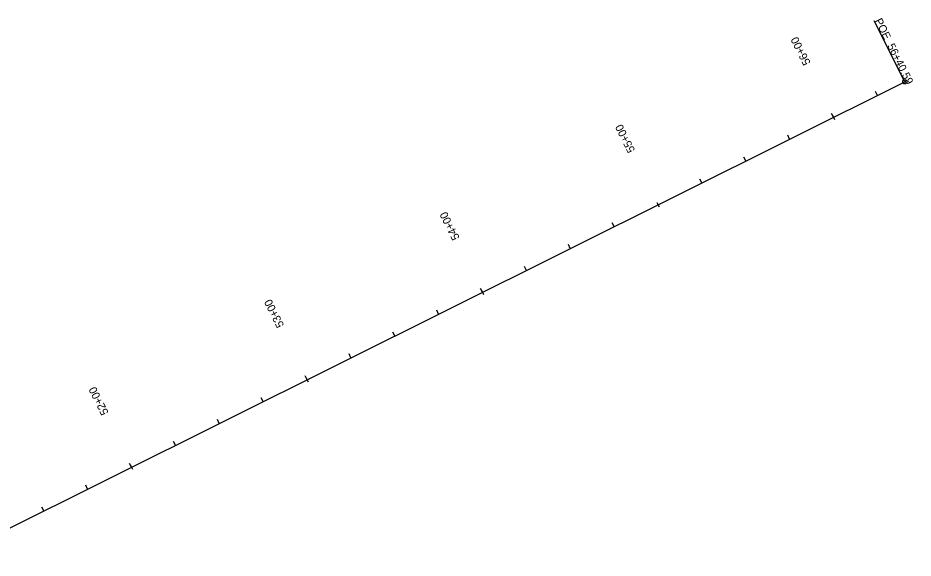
# Model space of a CAD drawing. Extents: x 21487884 to 21488802, y 8074558 to 8076894.
# Drawn here: x 21488345.4 to 21488801.9, y 8076618.7 to 8076894.3 of the extents above; entities that cross this region are included whole.
import ezdxf

# ---------------------------------------------------------------- set-up
doc = ezdxf.new("R2010")
doc.units = 0
for name, color, linetype in [('PS_BOLT', 7, 'Continuous'), ('PS_DIM', 7, 'Continuous'), ('PS_MID', 7, 'Continuous'), ('PS_SHAPE', 7, 'Continuous')]:
    doc.layers.add(name, color=color, linetype=linetype)

msp = doc.modelspace()

# ---------------------------------------------------------------- linework, layer by layer
at = {"layer": 'PS_BOLT'}
for p, q in [((21488761.31, 8076843.6), (21488760.33, 8076845.55)), ((21488671.27, 8076800.07), (21488672.36, 8076797.88)), ((21488582.32, 8076754.36), (21488581.35, 8076756.31)), ((21488492.83, 8076709.74), (21488491.85, 8076711.69)), ((21488403.33, 8076665.12), (21488402.36, 8076667.07))]:
    msp.add_line(p, q, dxfattribs=at)
at = {"layer": 'PS_DIM'}
msp.add_line((21488797.63, 8076861.71), (21488782.1, 8076892.86), dxfattribs=at)
msp.add_circle((21488797.63, 8076861.71), 1.07, dxfattribs=at)
at = {"layer": 'PS_MID'}
for p, q in [((21488783.68, 8076854.75), (21488782.7, 8076856.71)), ((21488760.76, 8076844.69), (21488761.85, 8076842.5)), ((21488738.93, 8076832.44), (21488737.96, 8076834.4)), ((21488716.56, 8076821.29), (21488715.58, 8076823.24)), ((21488694.19, 8076810.13), (21488693.21, 8076812.09)), ((21488671.27, 8076800.07), (21488672.36, 8076797.88)), ((21488649.44, 8076787.82), (21488648.46, 8076789.78)), ((21488627.07, 8076776.67), (21488626.09, 8076778.62)), ((21488604.69, 8076765.51), (21488603.72, 8076767.47)), ((21488581.77, 8076755.45), (21488582.87, 8076753.26)), ((21488559.95, 8076743.2), (21488558.97, 8076745.16)), ((21488537.57, 8076732.05), (21488536.6, 8076734)), ((21488515.2, 8076720.89), (21488514.23, 8076722.85)), ((21488492.28, 8076710.83), (21488493.37, 8076708.64)), ((21488470.45, 8076698.58), (21488469.48, 8076700.54)), ((21488448.08, 8076687.43), (21488447.11, 8076689.38)), ((21488425.71, 8076676.27), (21488424.73, 8076678.23)), ((21488402.79, 8076666.21), (21488403.88, 8076664.02)), ((21488380.96, 8076653.96), (21488379.99, 8076655.92)), ((21488358.59, 8076642.81), (21488357.61, 8076644.76))]:
    msp.add_line(p, q, dxfattribs=at)
at = {"layer": 'PS_SHAPE'}
msp.add_line((21488310.31, 8076618.73), (21488797.63, 8076861.71), dxfattribs=at)

# ---------------------------------------------------------------- texts
at = {"layer": 'PS_BOLT'}
msp.add_text('55+00', height=4.08, rotation=116.5007, dxfattribs=at).set_placement((21488660.25, 8076826.74))
at = {"layer": 'PS_DIM'}
for s, p in [('POE ', (21488782.17, 8076892.89)), ('56+40.59', (21488788.59, 8076880.03))]:
    msp.add_text(s, height=4.008, rotation=296.5007, dxfattribs=at).set_placement(p)
at = {"layer": 'PS_MID'}
for s, p in [('56+00', (21488749.74, 8076871.36)), ('55+00', (21488660.25, 8076826.74)), ('54+00', (21488570.76, 8076782.12)), ('53+00', (21488481.27, 8076737.49)), ('52+00', (21488391.77, 8076692.87))]:
    msp.add_text(s, height=4.08, rotation=116.5007, dxfattribs=at).set_placement(p)

doc.saveas('drawing.dxf')
